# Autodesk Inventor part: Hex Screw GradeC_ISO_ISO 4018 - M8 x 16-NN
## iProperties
Shininess: 64.0
Length Units: 11269
Angle Units: 11279
Time Units: 11290
Mass Units: 11283
Length Display Precision: 3
Angle Display Precision: 2
Compacted: True
Part Number: Hex Screw GradeC_ISO_ISO 4018 - M8 x 16-NN
Document SubType Name: Modeling
Created: 2006-11
Material: Par défaut
Designer: profs_sti
Density: 0.0
Volumn: 0.0
Area: 0.0
PropertySet Name: Model Information
Control State: 0
Master: False
Checked Out: False
Author: profs_sti
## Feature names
1. Base1
